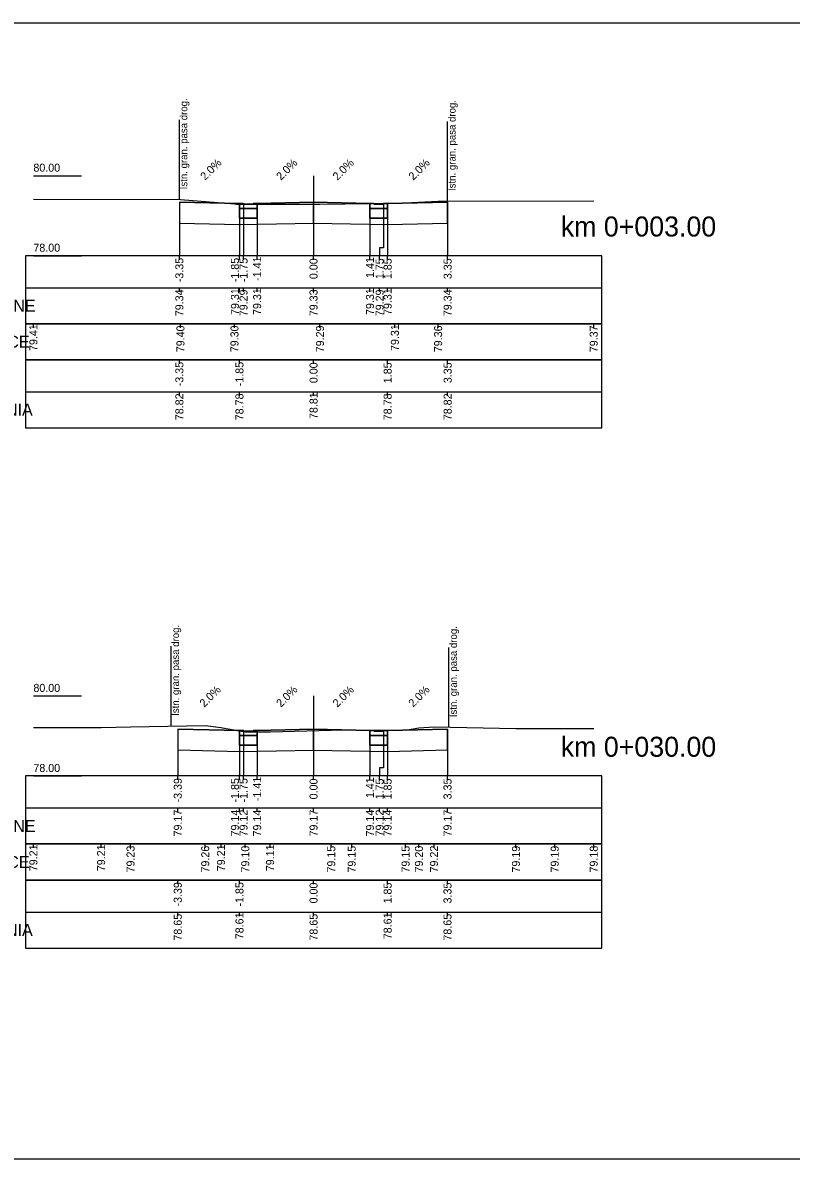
# Model space of a CAD drawing. Extents: x 7492871 to 7493499, y 5802964 to 5802992.
# Drawn here: x 7493372.33 to 7493391.54, y 5802963.88 to 5802992.28 of the extents above; entities that cross this region are included whole.
import ezdxf

# ---------------------------------------------------------------- set-up
doc = ezdxf.new("R2010")
doc.units = 0
for name, color, linetype in [('_wydruk', 7, 'Continuous'), ('opisy_ramki_pop', 7, 'Continuous'), ('pop_comp_kostka', 7, 'Continuous'), ('pop_comp_lawa', 7, 'Continuous'), ('pop_comp_scieralna', 7, 'Continuous'), ('pop_granica_istn', 7, 'Continuous'), ('pop_opis', 7, 'Continuous'), ('pop_os', 7, 'Continuous'), ('pop_pikietaz', 7, 'Continuous'), ('pop_teren', 7, 'Continuous')]:
    doc.layers.add(name, color=color, linetype=linetype)

msp = doc.modelspace()

# ---------------------------------------------------------------- linework, layer by layer
for points in [[(7493376.246, 5802987.795), (7493377.748, 5802987.765), (7493377.848, 5802987.765), (7493377.849, 5802987.745), (7493378.088, 5802987.745), (7493378.089, 5802987.765), (7493378.189, 5802987.765), (7493379.599, 5802987.793), (7493381.009, 5802987.765), (7493381.109, 5802987.765), (7493381.11, 5802987.745), (7493381.349, 5802987.745), (7493381.35, 5802987.765), (7493381.45, 5802987.765), (7493382.949, 5802987.795)], [(7493376.206, 5802974.63), (7493376.984, 5802974.614), (7493377.748, 5802974.599), (7493377.848, 5802974.599), (7493377.849, 5802974.579), (7493378.088, 5802974.579), (7493378.089, 5802974.599), (7493378.189, 5802974.599), (7493379.599, 5802974.627), (7493381.009, 5802974.599), (7493381.109, 5802974.599), (7493381.11, 5802974.579), (7493381.349, 5802974.579), (7493381.35, 5802974.599), (7493381.45, 5802974.599), (7493382.946, 5802974.629)]]:
    msp.add_lwpolyline(points)
at = {"layer": '_wydruk'}
msp.add_lwpolyline([(7492871.369, 5802992.281), (7493499.283, 5802992.281), (7493499.283, 5802963.881), (7492871.369, 5802963.881)], close=True, dxfattribs=at)
at = {"layer": 'opisy_ramki_pop'}
for points in [[(7493376.246, 5802987.275), (7493376.246, 5802986.659), (7493376.246, 5802986.659), (7493376.246, 5802986.459)], [(7493377.748, 5802987.236), (7493377.748, 5802986.659), (7493377.748, 5802986.659), (7493377.748, 5802986.459)], [(7493379.599, 5802987.273), (7493379.599, 5802986.659), (7493379.599, 5802986.659), (7493379.599, 5802986.459)], [(7493381.45, 5802987.236), (7493381.45, 5802986.659), (7493381.45, 5802986.659), (7493381.45, 5802986.459)], [(7493382.949, 5802987.275), (7493382.949, 5802986.659), (7493382.949, 5802986.659), (7493382.949, 5802986.459)], [(7493376.206, 5802974.11), (7493376.206, 5802973.659), (7493376.206, 5802973.659), (7493376.206, 5802973.459)], [(7493377.748, 5802974.07), (7493377.748, 5802973.659), (7493377.748, 5802973.659), (7493377.748, 5802973.459)], [(7493379.599, 5802974.107), (7493379.599, 5802973.659), (7493379.599, 5802973.659), (7493379.599, 5802973.459)], [(7493381.45, 5802974.07), (7493381.45, 5802973.659), (7493381.45, 5802973.659), (7493381.45, 5802973.459)], [(7493382.946, 5802974.109), (7493382.946, 5802973.659), (7493382.946, 5802973.659), (7493382.946, 5802973.459)]]:
    msp.add_lwpolyline(points, dxfattribs=at)
at = {"layer": 'pop_comp_kostka'}
for p, q in [((7493377.848, 5802987.765), (7493377.748, 5802987.765)), ((7493377.748, 5802987.765), (7493377.748, 5802987.635)), ((7493377.748, 5802987.635), (7493378.189, 5802987.635)), ((7493377.849, 5802987.745), (7493377.848, 5802987.765)), ((7493378.088, 5802987.745), (7493377.849, 5802987.745)), ((7493378.089, 5802987.765), (7493378.088, 5802987.745)), ((7493378.189, 5802987.765), (7493378.089, 5802987.765)), ((7493378.189, 5802987.635), (7493378.189, 5802987.765)), ((7493381.109, 5802987.765), (7493381.009, 5802987.765)), ((7493381.009, 5802987.765), (7493381.009, 5802987.635)), ((7493381.009, 5802987.635), (7493381.45, 5802987.635)), ((7493381.11, 5802987.745), (7493381.109, 5802987.765)), ((7493381.349, 5802987.745), (7493381.11, 5802987.745)), ((7493381.35, 5802987.765), (7493381.349, 5802987.745)), ((7493381.45, 5802987.765), (7493381.35, 5802987.765)), ((7493381.45, 5802987.635), (7493381.45, 5802987.765)), ((7493377.848, 5802974.599), (7493377.748, 5802974.599)), ((7493377.748, 5802974.599), (7493377.748, 5802974.469)), ((7493377.849, 5802974.579), (7493377.848, 5802974.599)), ((7493378.088, 5802974.579), (7493377.849, 5802974.579)), ((7493378.089, 5802974.599), (7493378.088, 5802974.579)), ((7493378.189, 5802974.599), (7493378.089, 5802974.599)), ((7493378.189, 5802974.469), (7493378.189, 5802974.599)), ((7493381.109, 5802974.599), (7493381.009, 5802974.599)), ((7493381.009, 5802974.599), (7493381.009, 5802974.469)), ((7493381.11, 5802974.579), (7493381.109, 5802974.599)), ((7493381.349, 5802974.579), (7493381.11, 5802974.579)), ((7493381.35, 5802974.599), (7493381.349, 5802974.579)), ((7493381.45, 5802974.599), (7493381.35, 5802974.599)), ((7493381.45, 5802974.469), (7493381.45, 5802974.599)), ((7493377.748, 5802974.469), (7493378.189, 5802974.469)), ((7493381.009, 5802974.469), (7493381.45, 5802974.469))]:
    msp.add_line(p, q, dxfattribs=at)
at = {"layer": 'pop_comp_lawa'}
for p, q in [((7493378.189, 5802987.635), (7493377.748, 5802987.635)), ((7493377.748, 5802987.635), (7493377.748, 5802987.395)), ((7493378.189, 5802987.395), (7493378.189, 5802987.635)), ((7493381.45, 5802987.635), (7493381.009, 5802987.635)), ((7493381.009, 5802987.635), (7493381.009, 5802987.395)), ((7493381.45, 5802987.395), (7493381.45, 5802987.635)), ((7493377.748, 5802987.395), (7493378.189, 5802987.395)), ((7493381.009, 5802987.395), (7493381.45, 5802987.395)), ((7493378.189, 5802974.469), (7493377.748, 5802974.469)), ((7493377.748, 5802974.469), (7493377.748, 5802974.229)), ((7493378.189, 5802974.229), (7493378.189, 5802974.469)), ((7493381.45, 5802974.469), (7493381.009, 5802974.469)), ((7493381.009, 5802974.469), (7493381.009, 5802974.229)), ((7493381.45, 5802974.229), (7493381.45, 5802974.469)), ((7493377.748, 5802974.229), (7493378.189, 5802974.229)), ((7493381.009, 5802974.229), (7493381.45, 5802974.229))]:
    msp.add_line(p, q, dxfattribs=at)
at = {"layer": 'pop_comp_scieralna'}
for p, q in [((7493377.748, 5802987.765), (7493376.246, 5802987.795)), ((7493376.246, 5802987.795), (7493376.246, 5802987.275)), ((7493377.748, 5802987.395), (7493377.748, 5802987.765)), ((7493379.599, 5802987.793), (7493378.189, 5802987.765)), ((7493378.189, 5802987.765), (7493378.189, 5802987.395)), ((7493379.599, 5802987.273), (7493379.599, 5802987.793)), ((7493381.009, 5802987.765), (7493379.599, 5802987.793)), ((7493379.599, 5802987.793), (7493379.599, 5802987.273)), ((7493381.009, 5802987.395), (7493381.009, 5802987.765)), ((7493382.949, 5802987.795), (7493381.45, 5802987.765)), ((7493381.45, 5802987.765), (7493381.45, 5802987.395)), ((7493382.949, 5802987.275), (7493382.949, 5802987.795)), ((7493378.189, 5802987.395), (7493377.748, 5802987.395)), ((7493381.45, 5802987.395), (7493381.009, 5802987.395)), ((7493376.246, 5802987.275), (7493377.748, 5802987.236)), ((7493377.748, 5802987.236), (7493379.599, 5802987.273)), ((7493379.599, 5802987.273), (7493381.45, 5802987.236)), ((7493381.45, 5802987.236), (7493382.949, 5802987.275)), ((7493377.748, 5802974.599), (7493376.206, 5802974.63)), ((7493376.206, 5802974.63), (7493376.206, 5802974.11)), ((7493377.748, 5802974.229), (7493377.748, 5802974.599)), ((7493379.599, 5802974.627), (7493378.189, 5802974.599)), ((7493378.189, 5802974.599), (7493378.189, 5802974.229)), ((7493379.599, 5802974.107), (7493379.599, 5802974.627)), ((7493381.009, 5802974.599), (7493379.599, 5802974.627)), ((7493379.599, 5802974.627), (7493379.599, 5802974.107)), ((7493381.009, 5802974.229), (7493381.009, 5802974.599)), ((7493382.946, 5802974.629), (7493381.45, 5802974.599)), ((7493381.45, 5802974.599), (7493381.45, 5802974.229)), ((7493382.946, 5802974.109), (7493382.946, 5802974.629)), ((7493376.206, 5802974.11), (7493377.748, 5802974.07)), ((7493378.189, 5802974.229), (7493377.748, 5802974.229)), ((7493377.748, 5802974.07), (7493379.599, 5802974.107)), ((7493379.599, 5802974.107), (7493381.45, 5802974.07)), ((7493381.45, 5802974.229), (7493381.009, 5802974.229)), ((7493381.45, 5802974.07), (7493382.946, 5802974.109))]:
    msp.add_line(p, q, dxfattribs=at)
at = {"layer": 'pop_granica_istn'}
for p, q in [((7493376.246, 5802988.357), (7493376.246, 5802989.857)), ((7493382.949, 5802988.314), (7493382.949, 5802989.814)), ((7493376.246, 5802987.857), (7493376.246, 5802988.357)), ((7493382.949, 5802987.814), (7493382.949, 5802988.314)), ((7493376.039, 5802975.199), (7493376.039, 5802976.699)), ((7493382.982, 5802975.166), (7493382.982, 5802976.666)), ((7493376.039, 5802974.699), (7493376.039, 5802975.199)), ((7493382.982, 5802974.666), (7493382.982, 5802975.166))]:
    msp.add_line(p, q, dxfattribs=at)
at = {"layer": 'pop_opis'}
for p, q in [((7493372.599, 5802988.459), (7493373.799, 5802988.459)), ((7493372.399, 5802986.459), (7493372.399, 5802984.759)), ((7493372.399, 5802986.459), (7493372.399, 5802984.759)), ((7493372.399, 5802986.459), (7493372.399, 5802984.759)), ((7493372.399, 5802986.459), (7493372.399, 5802984.759)), ((7493372.599, 5802986.459), (7493373.799, 5802986.459)), ((7493376.246, 5802986.359), (7493376.246, 5802986.459)), ((7493377.748, 5802986.359), (7493377.748, 5802986.459)), ((7493377.849, 5802986.359), (7493377.849, 5802986.459)), ((7493378.189, 5802986.359), (7493378.189, 5802986.459)), ((7493379.599, 5802986.359), (7493379.599, 5802986.459)), ((7493381.009, 5802986.359), (7493381.009, 5802986.459)), ((7493381.25, 5802986.359), (7493381.25, 5802986.459)), ((7493381.45, 5802986.359), (7493381.45, 5802986.459)), ((7493382.949, 5802986.359), (7493382.949, 5802986.459)), ((7493372.399, 5802985.659), (7493386.799, 5802985.659)), ((7493372.399, 5802985.659), (7493386.799, 5802985.659)), ((7493372.399, 5802985.659), (7493386.799, 5802985.659)), ((7493372.399, 5802985.659), (7493386.799, 5802985.659)), ((7493376.246, 5802985.559), (7493376.246, 5802985.659)), ((7493377.748, 5802985.559), (7493377.748, 5802985.659)), ((7493377.849, 5802985.559), (7493377.849, 5802985.659)), ((7493378.189, 5802985.559), (7493378.189, 5802985.659)), ((7493379.599, 5802985.559), (7493379.599, 5802985.659)), ((7493381.009, 5802985.559), (7493381.009, 5802985.659)), ((7493381.25, 5802985.559), (7493381.25, 5802985.659)), ((7493381.45, 5802985.559), (7493381.45, 5802985.659)), ((7493382.949, 5802985.559), (7493382.949, 5802985.659)), ((7493372.399, 5802984.759), (7493372.399, 5802983.859)), ((7493372.599, 5802984.659), (7493372.599, 5802984.759)), ((7493376.273, 5802984.659), (7493376.273, 5802984.759)), ((7493377.623, 5802984.659), (7493377.623, 5802984.759)), ((7493379.759, 5802984.659), (7493379.759, 5802984.759)), ((7493381.631, 5802984.659), (7493381.631, 5802984.759)), ((7493382.711, 5802984.659), (7493382.711, 5802984.759)), ((7493386.599, 5802984.659), (7493386.599, 5802984.759)), ((7493372.399, 5802983.859), (7493372.399, 5802982.159)), ((7493376.246, 5802983.759), (7493376.246, 5802983.859)), ((7493377.748, 5802983.759), (7493377.748, 5802983.859)), ((7493379.599, 5802983.759), (7493379.599, 5802983.859)), ((7493381.45, 5802983.759), (7493381.45, 5802983.859)), ((7493382.949, 5802983.759), (7493382.949, 5802983.859)), ((7493372.399, 5802983.059), (7493386.799, 5802983.059)), ((7493376.246, 5802982.959), (7493376.246, 5802983.059)), ((7493377.748, 5802982.959), (7493377.748, 5802983.059)), ((7493379.599, 5802982.959), (7493379.599, 5802983.059)), ((7493381.45, 5802982.959), (7493381.45, 5802983.059)), ((7493382.949, 5802982.959), (7493382.949, 5802983.059)), ((7493372.599, 5802975.459), (7493373.799, 5802975.459)), ((7493372.399, 5802973.459), (7493372.399, 5802971.759)), ((7493372.399, 5802973.459), (7493372.399, 5802971.759)), ((7493372.399, 5802973.459), (7493372.399, 5802971.759)), ((7493372.399, 5802973.459), (7493372.399, 5802971.759)), ((7493372.599, 5802973.459), (7493373.799, 5802973.459)), ((7493376.206, 5802973.359), (7493376.206, 5802973.459)), ((7493377.748, 5802973.359), (7493377.748, 5802973.459)), ((7493377.849, 5802973.359), (7493377.849, 5802973.459)), ((7493378.189, 5802973.359), (7493378.189, 5802973.459)), ((7493379.599, 5802973.359), (7493379.599, 5802973.459)), ((7493381.009, 5802973.359), (7493381.009, 5802973.459)), ((7493381.25, 5802973.359), (7493381.25, 5802973.459)), ((7493381.45, 5802973.359), (7493381.45, 5802973.459)), ((7493382.946, 5802973.359), (7493382.946, 5802973.459)), ((7493372.399, 5802972.659), (7493386.799, 5802972.659)), ((7493372.399, 5802972.659), (7493386.799, 5802972.659)), ((7493372.399, 5802972.659), (7493386.799, 5802972.659)), ((7493372.399, 5802972.659), (7493386.799, 5802972.659)), ((7493376.206, 5802972.559), (7493376.206, 5802972.659)), ((7493377.748, 5802972.559), (7493377.748, 5802972.659)), ((7493377.849, 5802972.559), (7493377.849, 5802972.659)), ((7493378.189, 5802972.559), (7493378.189, 5802972.659)), ((7493379.599, 5802972.559), (7493379.599, 5802972.659)), ((7493381.009, 5802972.559), (7493381.009, 5802972.659)), ((7493381.25, 5802972.559), (7493381.25, 5802972.659)), ((7493381.45, 5802972.559), (7493381.45, 5802972.659)), ((7493382.946, 5802972.559), (7493382.946, 5802972.659)), ((7493372.399, 5802971.759), (7493372.399, 5802970.859)), ((7493372.599, 5802971.659), (7493372.599, 5802971.759)), ((7493374.291, 5802971.659), (7493374.291, 5802971.759)), ((7493375.026, 5802971.659), (7493375.026, 5802971.759)), ((7493376.892, 5802971.659), (7493376.892, 5802971.759)), ((7493377.287, 5802971.659), (7493377.287, 5802971.759)), ((7493377.893, 5802971.659), (7493377.893, 5802971.759)), ((7493378.513, 5802971.659), (7493378.513, 5802971.759)), ((7493380.041, 5802971.659), (7493380.041, 5802971.759)), ((7493380.552, 5802971.659), (7493380.552, 5802971.759)), ((7493381.899, 5802971.659), (7493381.899, 5802971.759)), ((7493382.232, 5802971.659), (7493382.232, 5802971.759)), ((7493382.609, 5802971.659), (7493382.609, 5802971.759)), ((7493384.657, 5802971.659), (7493384.657, 5802971.759)), ((7493385.625, 5802971.659), (7493385.625, 5802971.759)), ((7493386.599, 5802971.659), (7493386.599, 5802971.759)), ((7493372.399, 5802970.859), (7493372.399, 5802969.159)), ((7493376.206, 5802970.759), (7493376.206, 5802970.859)), ((7493377.748, 5802970.759), (7493377.748, 5802970.859)), ((7493379.599, 5802970.759), (7493379.599, 5802970.859)), ((7493381.45, 5802970.759), (7493381.45, 5802970.859)), ((7493382.946, 5802970.759), (7493382.946, 5802970.859)), ((7493372.399, 5802970.059), (7493386.799, 5802970.059)), ((7493376.206, 5802969.959), (7493376.206, 5802970.059)), ((7493377.748, 5802969.959), (7493377.748, 5802970.059)), ((7493379.599, 5802969.959), (7493379.599, 5802970.059)), ((7493381.45, 5802969.959), (7493381.45, 5802970.059)), ((7493382.946, 5802969.959), (7493382.946, 5802970.059))]:
    msp.add_line(p, q, dxfattribs=at)
for points in [[(7493376.246, 5802987.795), (7493376.246, 5802986.659), (7493376.246, 5802986.659), (7493376.246, 5802986.459)], [(7493377.748, 5802987.765), (7493377.748, 5802986.659), (7493377.748, 5802986.659), (7493377.748, 5802986.459)], [(7493377.849, 5802987.745), (7493377.849, 5802986.659), (7493377.849, 5802986.659), (7493377.849, 5802986.459)], [(7493378.189, 5802987.765), (7493378.189, 5802986.659), (7493378.189, 5802986.659), (7493378.189, 5802986.459)], [(7493379.599, 5802987.793), (7493379.599, 5802986.659), (7493379.599, 5802986.659), (7493379.599, 5802986.459)], [(7493381.009, 5802987.765), (7493381.009, 5802986.659), (7493381.009, 5802986.659), (7493381.009, 5802986.459)], [(7493381.349, 5802987.745), (7493381.349, 5802986.659), (7493381.25, 5802986.659), (7493381.25, 5802986.459)], [(7493381.45, 5802987.765), (7493381.45, 5802986.659), (7493381.45, 5802986.659), (7493381.45, 5802986.459)], [(7493382.949, 5802987.795), (7493382.949, 5802986.659), (7493382.949, 5802986.659), (7493382.949, 5802986.459)], [(7493376.206, 5802974.63), (7493376.206, 5802973.659), (7493376.206, 5802973.659), (7493376.206, 5802973.459)], [(7493377.748, 5802974.599), (7493377.748, 5802973.659), (7493377.748, 5802973.659), (7493377.748, 5802973.459)], [(7493377.849, 5802974.579), (7493377.849, 5802973.659), (7493377.849, 5802973.659), (7493377.849, 5802973.459)], [(7493378.189, 5802974.599), (7493378.189, 5802973.659), (7493378.189, 5802973.659), (7493378.189, 5802973.459)], [(7493379.599, 5802974.627), (7493379.599, 5802973.659), (7493379.599, 5802973.659), (7493379.599, 5802973.459)], [(7493381.009, 5802974.599), (7493381.009, 5802973.659), (7493381.009, 5802973.659), (7493381.009, 5802973.459)], [(7493381.349, 5802974.579), (7493381.349, 5802973.659), (7493381.25, 5802973.659), (7493381.25, 5802973.459)], [(7493381.45, 5802974.599), (7493381.45, 5802973.659), (7493381.45, 5802973.659), (7493381.45, 5802973.459)], [(7493382.946, 5802974.629), (7493382.946, 5802973.659), (7493382.946, 5802973.659), (7493382.946, 5802973.459)]]:
    msp.add_lwpolyline(points, dxfattribs=at)
for points in [[(7493372.399, 5802986.459), (7493372.399, 5802984.759), (7493386.799, 5802984.759), (7493386.799, 5802986.459)], [(7493372.399, 5802986.459), (7493372.399, 5802984.759), (7493386.799, 5802984.759), (7493386.799, 5802986.459)], [(7493372.399, 5802986.459), (7493372.399, 5802984.759), (7493386.799, 5802984.759), (7493386.799, 5802986.459)], [(7493372.399, 5802986.459), (7493372.399, 5802984.759), (7493386.799, 5802984.759), (7493386.799, 5802986.459)], [(7493372.399, 5802984.759), (7493372.399, 5802983.859), (7493386.799, 5802983.859), (7493386.799, 5802984.759)], [(7493372.399, 5802983.859), (7493372.399, 5802982.159), (7493386.799, 5802982.159), (7493386.799, 5802983.859)], [(7493372.399, 5802973.459), (7493372.399, 5802971.759), (7493386.799, 5802971.759), (7493386.799, 5802973.459)], [(7493372.399, 5802973.459), (7493372.399, 5802971.759), (7493386.799, 5802971.759), (7493386.799, 5802973.459)], [(7493372.399, 5802973.459), (7493372.399, 5802971.759), (7493386.799, 5802971.759), (7493386.799, 5802973.459)], [(7493372.399, 5802973.459), (7493372.399, 5802971.759), (7493386.799, 5802971.759), (7493386.799, 5802973.459)], [(7493372.399, 5802971.759), (7493372.399, 5802970.859), (7493386.799, 5802970.859), (7493386.799, 5802971.759)], [(7493372.399, 5802970.859), (7493372.399, 5802969.159), (7493386.799, 5802969.159), (7493386.799, 5802970.859)]]:
    msp.add_lwpolyline(points, close=True, dxfattribs=at)
at = {"layer": 'pop_os'}
for p, q in [((7493379.599, 5802988.459), (7493379.599, 5802986.459)), ((7493379.599, 5802975.459), (7493379.599, 5802973.459))]:
    msp.add_line(p, q, dxfattribs=at)
at = {"layer": 'pop_teren'}
for points in [[(7493372.599, 5802987.87), (7493376.273, 5802987.861), (7493377.623, 5802987.757), (7493377.674, 5802987.751), (7493377.678, 5802987.75), (7493379.759, 5802987.749), (7493381.631, 5802987.768), (7493381.684, 5802987.768), (7493381.72, 5802987.768), (7493382.711, 5802987.818), (7493382.727, 5802987.821), (7493386.599, 5802987.83)], [(7493372.599, 5802974.667), (7493374.291, 5802974.673), (7493375.026, 5802974.686), (7493376.892, 5802974.716), (7493377.287, 5802974.667), (7493377.32, 5802974.66), (7493377.893, 5802974.563), (7493378.513, 5802974.565), (7493380.041, 5802974.607), (7493380.552, 5802974.61), (7493381.899, 5802974.606), (7493382.232, 5802974.659), (7493382.609, 5802974.683), (7493384.657, 5802974.644), (7493385.625, 5802974.644), (7493386.599, 5802974.643)]]:
    msp.add_lwpolyline(points, dxfattribs=at)

# ---------------------------------------------------------------- texts
at = {"layer": 'pop_granica_istn'}
for p in [(7493376.444, 5802988.118), (7493383.147, 5802988.075), (7493376.238, 5802974.96), (7493383.18, 5802974.928)]:
    msp.add_text('Istn. gran. pasa drog.', height=0.18, rotation=90, dxfattribs=at).set_placement(p)
at = {"layer": 'pop_opis'}
for s, height, p in [('80.00', 0.2, (7493372.599, 5802988.559)), ('78.00', 0.2, (7493372.599, 5802986.559)), ('RZĘDNE PROJEKTOWANE', 0.3, (7493367.527, 5802985.059)), ('RZĘDNE PROJEKTOWANE', 0.3, (7493367.527, 5802985.059)), ('RZĘDNE PROJEKTOWANE', 0.3, (7493367.527, 5802985.059)), ('RZĘDNE PROJEKTOWANE', 0.3, (7493367.527, 5802985.059)), ('RZĘDNE ISTNIEJĄCE', 0.3, (7493368.424, 5802984.159)), ('RZĘDNE KORYTOWANIA', 0.3, (7493367.813, 5802982.459)), ('80.00', 0.2, (7493372.599, 5802975.559)), ('78.00', 0.2, (7493372.599, 5802973.559)), ('RZĘDNE PROJEKTOWANE', 0.3, (7493367.527, 5802972.059)), ('RZĘDNE PROJEKTOWANE', 0.3, (7493367.527, 5802972.059)), ('RZĘDNE PROJEKTOWANE', 0.3, (7493367.527, 5802972.059)), ('RZĘDNE PROJEKTOWANE', 0.3, (7493367.527, 5802972.059)), ('RZĘDNE ISTNIEJĄCE', 0.3, (7493368.424, 5802971.159)), ('RZĘDNE KORYTOWANIA', 0.3, (7493367.813, 5802969.459))]:
    msp.add_text(s, height=height, dxfattribs=at).set_placement(p)
for s, rotation, p in [('2.0%', 45, (7493376.889, 5802988.33)), ('2.0%', 45, (7493378.785, 5802988.329)), ('2.0%', 45, (7493380.195, 5802988.329)), ('2.0%', 45, (7493382.091, 5802988.33)), ('-3.35', 90, (7493376.346, 5802985.796)), ('-1.85', 90, (7493377.735, 5802985.796)), ('-1.75', 90, (7493377.949, 5802985.796)), ('-1.41', 90, (7493378.289, 5802985.829)), ('0.00', 90, (7493379.699, 5802985.874)), ('1.41', 90, (7493381.109, 5802985.905)), ('1.75', 90, (7493381.35, 5802985.873)), ('1.85', 90, (7493381.55, 5802985.873)), ('3.35', 90, (7493383.049, 5802985.873)), ('79.31', 90, (7493377.735, 5802984.978)), ('79.31', 90, (7493378.289, 5802984.978)), ('79.31', 90, (7493381.109, 5802984.978)), ('79.31', 90, (7493381.55, 5802984.978)), ('79.34', 90, (7493376.346, 5802984.947)), ('79.29', 90, (7493377.949, 5802984.946)), ('79.33', 90, (7493379.699, 5802984.947)), ('79.29', 90, (7493381.35, 5802984.946)), ('79.34', 90, (7493383.049, 5802984.947)), ('79.41', 90, (7493372.699, 5802984.078)), ('79.40', 90, (7493376.373, 5802984.047)), ('79.30', 90, (7493377.723, 5802984.047)), ('79.29', 90, (7493379.859, 5802984.046)), ('79.31', 90, (7493381.731, 5802984.078)), ('79.36', 90, (7493382.811, 5802984.047)), ('79.37', 90, (7493386.699, 5802984.047)), ('-3.35', 90, (7493376.346, 5802983.196)), ('-1.85', 90, (7493377.848, 5802983.196)), ('0.00', 90, (7493379.699, 5802983.274)), ('1.85', 90, (7493381.55, 5802983.273)), ('3.35', 90, (7493383.049, 5802983.273)), ('78.82', 90, (7493376.346, 5802982.348)), ('78.78', 90, (7493377.848, 5802982.346)), ('78.81', 90, (7493379.699, 5802982.378)), ('78.78', 90, (7493381.55, 5802982.346)), ('78.82', 90, (7493383.049, 5802982.348)), ('2.0%', 45, (7493376.869, 5802975.164)), ('2.0%', 45, (7493378.785, 5802975.163)), ('2.0%', 45, (7493380.195, 5802975.163)), ('2.0%', 45, (7493382.089, 5802975.164)), ('-1.41', 90, (7493378.289, 5802972.829)), ('-3.39', 90, (7493376.306, 5802972.797)), ('-1.85', 90, (7493377.735, 5802972.796)), ('-1.75', 90, (7493377.949, 5802972.796)), ('0.00', 90, (7493379.699, 5802972.874)), ('1.41', 90, (7493381.109, 5802972.905)), ('1.75', 90, (7493381.35, 5802972.873)), ('1.85', 90, (7493381.55, 5802972.873)), ('3.35', 90, (7493383.046, 5802972.873)), ('79.17', 90, (7493376.306, 5802971.947)), ('79.14', 90, (7493377.735, 5802971.947)), ('79.12', 90, (7493377.949, 5802971.948)), ('79.14', 90, (7493378.289, 5802971.947)), ('79.17', 90, (7493379.699, 5802971.947)), ('79.14', 90, (7493381.109, 5802971.947)), ('79.12', 90, (7493381.35, 5802971.948)), ('79.14', 90, (7493381.55, 5802971.947)), ('79.17', 90, (7493383.046, 5802971.947)), ('79.21', 90, (7493372.699, 5802971.078)), ('79.21', 90, (7493374.391, 5802971.078)), ('79.21', 90, (7493377.387, 5802971.078)), ('79.11', 90, (7493378.613, 5802971.078)), ('79.23', 90, (7493375.126, 5802971.047)), ('79.26', 90, (7493376.992, 5802971.047)), ('79.10', 90, (7493377.993, 5802971.047)), ('79.15', 90, (7493380.141, 5802971.045)), ('79.15', 90, (7493380.652, 5802971.045)), ('79.15', 90, (7493381.999, 5802971.045)), ('79.20', 90, (7493382.332, 5802971.047)), ('79.22', 90, (7493382.709, 5802971.048)), ('79.19', 90, (7493384.757, 5802971.046)), ('79.19', 90, (7493385.725, 5802971.046)), ('79.18', 90, (7493386.699, 5802971.046)), ('-3.39', 90, (7493376.306, 5802970.197)), ('-1.85', 90, (7493377.848, 5802970.196)), ('0.00', 90, (7493379.699, 5802970.274)), ('1.85', 90, (7493381.55, 5802970.273)), ('3.35', 90, (7493383.046, 5802970.273)), ('78.61', 90, (7493377.848, 5802969.378)), ('78.61', 90, (7493381.55, 5802969.378)), ('78.65', 90, (7493376.306, 5802969.345)), ('78.65', 90, (7493379.699, 5802969.345)), ('78.65', 90, (7493383.046, 5802969.345))]:
    msp.add_text(s, height=0.2, rotation=rotation, dxfattribs=at).set_placement(p)
at = {"layer": 'pop_pikietaz'}
for s, p in [('km 0+003.00', (7493385.775, 5802986.939)), ('km 0+030.00', (7493385.775, 5802973.939))]:
    msp.add_text(s, height=0.5, dxfattribs=at).set_placement(p)

doc.saveas('drawing.dxf')
